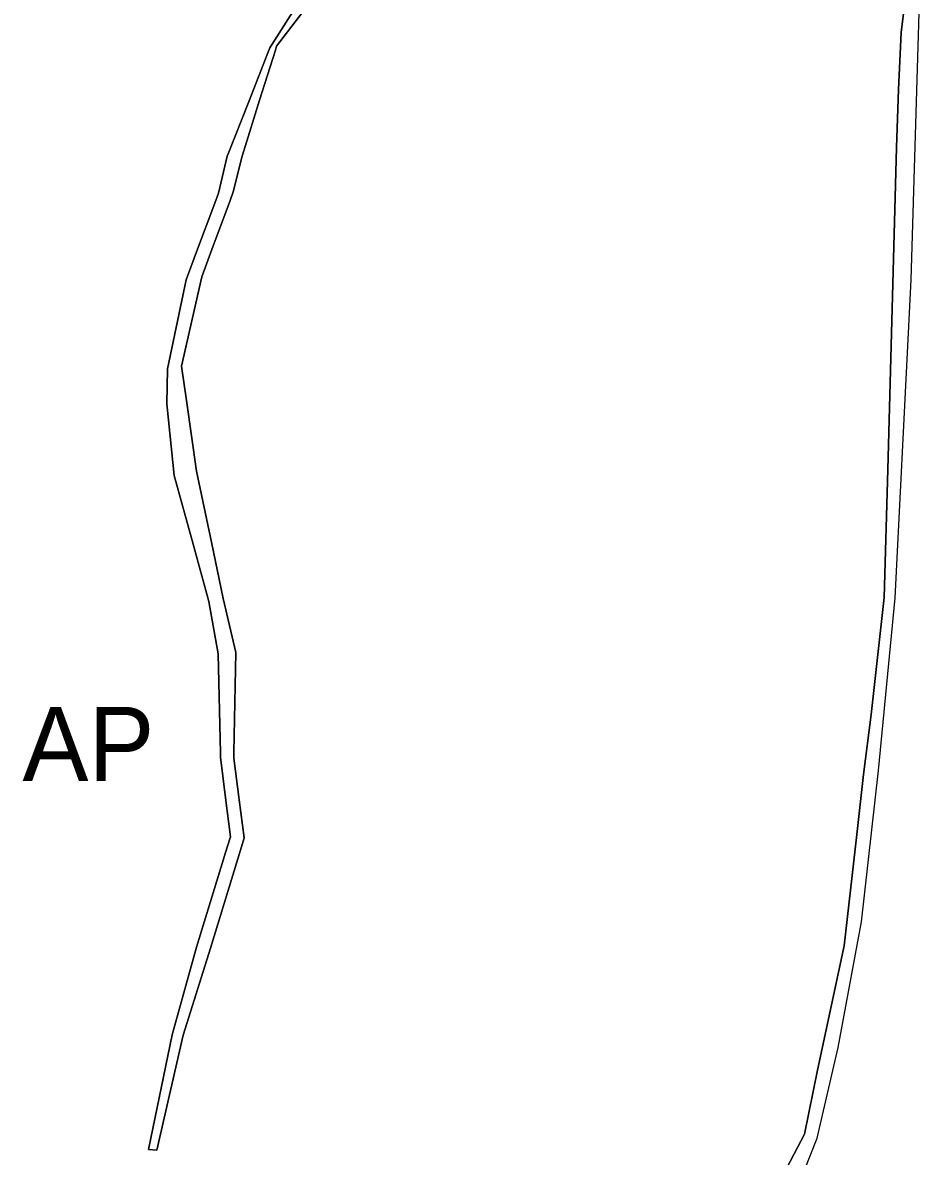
# Model space of a CAD drawing. Extents: x -555509 to -553005, y -1186756 to -1182560.
# Drawn here: x -553439.4 to -553269.7, y -1183694.3 to -1183479.6 of the extents above; entities that cross this region are included whole.
import ezdxf

# ---------------------------------------------------------------- set-up
doc = ezdxf.new("R2010")
doc.units = 0
for name, color, linetype in [('Level 26', 7, 'Continuous'), ('Level 59', 7, 'Continuous'), ('OBRYS_PLOCH', 7, 'Continuous'), ('stav_AP', 7, 'Continuous'), ('stav_ZK', 7, 'Continuous')]:
    doc.layers.add(name, color=color, linetype=linetype)

msp = doc.modelspace()

# ---------------------------------------------------------------- linework, layer by layer
at = {"layer": 'Level 26'}
for p, q in [((-553271.84, -1183471.16), (-553273.12, -1183481.48)), ((-553271.2, -1183528.31), (-553269.67, -1183477.71)), ((-553273.12, -1183481.48), (-553273.58, -1183492.27)), ((-553273.58, -1183492.27), (-553273.96, -1183503.21)), ((-553273.96, -1183503.21), (-553274.81, -1183533.7)), ((-553274.27, -1183588.5), (-553271.2, -1183528.31)), ((-553274.81, -1183533.7), (-553275.62, -1183564.2)), ((-553275.62, -1183564.2), (-553276.31, -1183588.43)), ((-553276.31, -1183588.43), (-553278.78, -1183610.59)), ((-553277.37, -1183621.21), (-553274.27, -1183588.5)), ((-553278.78, -1183610.59), (-553280.24, -1183621.99)), ((-553280.24, -1183621.99), (-553281.51, -1183633.35)), ((-553280.64, -1183649.89), (-553277.37, -1183621.21)), ((-553281.51, -1183633.35), (-553283.92, -1183654.41)), ((-553285.02, -1183673.67), (-553280.64, -1183649.89)), ((-553283.92, -1183654.41), (-553288.93, -1183677.96)), ((-553289.02, -1183690.81), (-553285.02, -1183673.67)), ((-553288.93, -1183677.96), (-553291.41, -1183690.06)), ((-553291.41, -1183690.06), (-553302.02, -1183710.22))]:
    msp.add_line(p, q, dxfattribs=at)
msp.add_lwpolyline([(-553303.19, -1183731.69), (-553297.87, -1183713.28), (-553289.02, -1183690.81)], dxfattribs=at)
at = {"layer": 'OBRYS_PLOCH'}
for p, q in [((-553391.32, -1183484.04), (-553380.16, -1183469.46)), ((-553380.16, -1183469.46), (-553391.32, -1183484.04)), ((-553383.76, -1183470.34), (-553392.58, -1183484.35)), ((-553392.58, -1183484.35), (-553383.76, -1183470.34)), ((-553271.84, -1183471.16), (-553273.12, -1183481.48)), ((-553273.12, -1183481.48), (-553271.84, -1183471.16)), ((-553271.2, -1183528.31), (-553269.67, -1183477.71)), ((-553273.12, -1183481.48), (-553273.58, -1183492.27)), ((-553273.58, -1183492.27), (-553273.12, -1183481.48)), ((-553394.53, -1183494.29), (-553391.55, -1183484.77)), ((-553391.55, -1183484.77), (-553394.53, -1183494.29)), ((-553392.58, -1183484.35), (-553392.85, -1183485.02)), ((-553392.85, -1183485.02), (-553392.58, -1183484.35)), ((-553391.55, -1183484.77), (-553391.32, -1183484.04)), ((-553391.32, -1183484.04), (-553391.55, -1183484.77)), ((-553392.85, -1183485.02), (-553396.66, -1183494.7)), ((-553396.66, -1183494.7), (-553392.85, -1183485.02)), ((-553273.58, -1183492.27), (-553273.96, -1183503.21)), ((-553273.96, -1183503.21), (-553273.58, -1183492.27)), ((-553396.66, -1183494.7), (-553400.49, -1183504.4)), ((-553400.49, -1183504.4), (-553396.66, -1183494.7)), ((-553397.53, -1183503.84), (-553394.53, -1183494.29)), ((-553394.53, -1183494.29), (-553397.53, -1183503.84)), ((-553397.9, -1183505.04), (-553397.53, -1183503.84)), ((-553397.53, -1183503.84), (-553397.9, -1183505.04)), ((-553273.96, -1183503.21), (-553274.81, -1183533.7)), ((-553274.81, -1183533.7), (-553273.96, -1183503.21)), ((-553400.66, -1183504.85), (-553402.33, -1183511.88)), ((-553402.33, -1183511.88), (-553400.66, -1183504.85)), ((-553400.49, -1183504.4), (-553400.66, -1183504.85)), ((-553400.66, -1183504.85), (-553400.49, -1183504.4)), ((-553399.46, -1183511.44), (-553397.9, -1183505.04)), ((-553397.9, -1183505.04), (-553399.46, -1183511.44)), ((-553402.33, -1183511.88), (-553403.02, -1183513.75)), ((-553403.02, -1183513.75), (-553402.33, -1183511.88)), ((-553400.14, -1183513.27), (-553399.46, -1183511.44)), ((-553399.46, -1183511.44), (-553400.14, -1183513.27)), ((-553403.02, -1183513.75), (-553406.46, -1183522.99)), ((-553406.46, -1183522.99), (-553403.02, -1183513.75)), ((-553403.59, -1183522.56), (-553400.14, -1183513.27)), ((-553400.14, -1183513.27), (-553403.59, -1183522.56)), ((-553406.46, -1183522.99), (-553408.45, -1183528.32)), ((-553408.45, -1183528.32), (-553406.46, -1183522.99)), ((-553405.5, -1183527.73), (-553403.59, -1183522.56)), ((-553403.59, -1183522.56), (-553405.5, -1183527.73)), ((-553409.35, -1183544.62), (-553405.5, -1183527.73)), ((-553405.5, -1183527.73), (-553409.35, -1183544.62)), ((-553408.45, -1183528.32), (-553412, -1183545.16)), ((-553412, -1183545.16), (-553408.45, -1183528.32)), ((-553274.27, -1183588.5), (-553271.2, -1183528.31)), ((-553274.81, -1183533.7), (-553275.62, -1183564.2)), ((-553275.62, -1183564.2), (-553274.81, -1183533.7)), ((-553408.4, -1183551.17), (-553409.35, -1183544.62)), ((-553409.35, -1183544.62), (-553408.4, -1183551.17)), ((-553412, -1183545.16), (-553412.1, -1183551.77)), ((-553412.1, -1183551.77), (-553412, -1183545.16)), ((-553406.47, -1183564.52), (-553408.4, -1183551.17)), ((-553408.4, -1183551.17), (-553406.47, -1183564.52)), ((-553412.1, -1183551.77), (-553410.69, -1183565.36)), ((-553410.69, -1183565.36), (-553412.1, -1183551.77)), ((-553275.62, -1183564.2), (-553276.31, -1183588.43)), ((-553276.31, -1183588.43), (-553275.62, -1183564.2)), ((-553410.69, -1183565.36), (-553407.14, -1183578.33)), ((-553407.14, -1183578.33), (-553410.69, -1183565.36)), ((-553403.65, -1183577.98), (-553406.47, -1183564.52)), ((-553406.47, -1183564.52), (-553403.65, -1183577.98)), ((-553407.14, -1183578.33), (-553404.16, -1183589.2)), ((-553404.16, -1183589.2), (-553407.14, -1183578.33)), ((-553401.41, -1183588.64), (-553403.65, -1183577.98)), ((-553403.65, -1183577.98), (-553401.41, -1183588.64)), ((-553404.16, -1183589.2), (-553402.35, -1183599.13)), ((-553402.35, -1183599.13), (-553404.16, -1183589.2)), ((-553399.06, -1183598.85), (-553401.41, -1183588.64)), ((-553401.41, -1183588.64), (-553399.06, -1183598.85)), ((-553276.31, -1183588.43), (-553278.78, -1183610.59)), ((-553278.78, -1183610.59), (-553276.31, -1183588.43)), ((-553277.37, -1183621.21), (-553274.27, -1183588.5)), ((-553402.35, -1183599.13), (-553401.96, -1183617.95)), ((-553401.96, -1183617.95), (-553402.35, -1183599.13)), ((-553399.39, -1183617.8), (-553399.06, -1183598.85)), ((-553399.06, -1183598.85), (-553399.39, -1183617.8)), ((-553278.78, -1183610.59), (-553280.24, -1183621.99)), ((-553280.24, -1183621.99), (-553278.78, -1183610.59)), ((-553401.96, -1183617.95), (-553401.94, -1183618.66)), ((-553401.94, -1183618.66), (-553401.96, -1183617.95)), ((-553399.41, -1183618.84), (-553399.39, -1183617.8)), ((-553399.39, -1183617.8), (-553399.41, -1183618.84)), ((-553401.94, -1183618.66), (-553400.91, -1183626.86)), ((-553400.91, -1183626.86), (-553401.94, -1183618.66)), ((-553398.39, -1183626.76), (-553399.41, -1183618.84)), ((-553399.41, -1183618.84), (-553398.39, -1183626.76)), ((-553280.24, -1183621.99), (-553281.51, -1183633.35)), ((-553281.51, -1183633.35), (-553280.24, -1183621.99)), ((-553280.64, -1183649.89), (-553277.37, -1183621.21)), ((-553400.91, -1183626.86), (-553400.05, -1183633.75)), ((-553400.05, -1183633.75), (-553400.91, -1183626.86)), ((-553397.45, -1183633.93), (-553398.39, -1183626.76)), ((-553398.39, -1183626.76), (-553397.45, -1183633.93)), ((-553400.05, -1183633.75), (-553400.66, -1183635.71)), ((-553400.66, -1183635.71), (-553400.05, -1183633.75)), ((-553397.98, -1183635.66), (-553397.45, -1183633.93)), ((-553397.45, -1183633.93), (-553397.98, -1183635.66)), ((-553281.51, -1183633.35), (-553283.92, -1183654.41)), ((-553283.92, -1183654.41), (-553281.51, -1183633.35)), ((-553400.66, -1183635.71), (-553406.51, -1183654.66)), ((-553406.51, -1183654.66), (-553400.66, -1183635.71)), ((-553403.82, -1183654.85), (-553397.98, -1183635.66)), ((-553397.98, -1183635.66), (-553403.82, -1183654.85)), ((-553285.02, -1183673.67), (-553280.64, -1183649.89)), ((-553283.92, -1183654.41), (-553288.93, -1183677.96)), ((-553288.93, -1183677.96), (-553283.92, -1183654.41)), ((-553406.51, -1183654.66), (-553411.11, -1183671.23)), ((-553411.11, -1183671.23), (-553406.51, -1183654.66)), ((-553408.98, -1183671.33), (-553403.82, -1183654.85)), ((-553403.82, -1183654.85), (-553408.98, -1183671.33)), ((-553411.11, -1183671.23), (-553415.59, -1183693)), ((-553415.59, -1183693), (-553411.11, -1183671.23)), ((-553414, -1183693.11), (-553408.98, -1183671.33)), ((-553408.98, -1183671.33), (-553414, -1183693.11)), ((-553289.02, -1183690.81), (-553285.02, -1183673.67)), ((-553288.93, -1183677.96), (-553291.41, -1183690.06)), ((-553291.41, -1183690.06), (-553288.93, -1183677.96)), ((-553291.41, -1183690.06), (-553302.02, -1183710.22)), ((-553302.02, -1183710.22), (-553291.41, -1183690.06)), ((-553415.59, -1183693), (-553414, -1183693.11)), ((-553414, -1183693.11), (-553415.59, -1183693))]:
    msp.add_line(p, q, dxfattribs=at)
msp.add_lwpolyline([(-553303.19, -1183731.69), (-553297.87, -1183713.28), (-553289.02, -1183690.81)], dxfattribs=at)
at = {"layer": 'stav_AP'}
for p, q in [((-553380.16, -1183469.46), (-553391.32, -1183484.04)), ((-553392.58, -1183484.35), (-553383.76, -1183470.34)), ((-553273.12, -1183481.48), (-553271.84, -1183471.16)), ((-553273.58, -1183492.27), (-553273.12, -1183481.48)), ((-553391.55, -1183484.77), (-553394.53, -1183494.29)), ((-553392.85, -1183485.02), (-553392.58, -1183484.35)), ((-553391.32, -1183484.04), (-553391.55, -1183484.77)), ((-553396.66, -1183494.7), (-553392.85, -1183485.02)), ((-553273.96, -1183503.21), (-553273.58, -1183492.27)), ((-553400.49, -1183504.4), (-553396.66, -1183494.7)), ((-553394.53, -1183494.29), (-553397.53, -1183503.84)), ((-553397.53, -1183503.84), (-553397.9, -1183505.04)), ((-553274.81, -1183533.7), (-553273.96, -1183503.21)), ((-553402.33, -1183511.88), (-553400.66, -1183504.85)), ((-553400.66, -1183504.85), (-553400.49, -1183504.4)), ((-553397.9, -1183505.04), (-553399.46, -1183511.44)), ((-553403.02, -1183513.75), (-553402.33, -1183511.88)), ((-553399.46, -1183511.44), (-553400.14, -1183513.27)), ((-553406.46, -1183522.99), (-553403.02, -1183513.75)), ((-553400.14, -1183513.27), (-553403.59, -1183522.56)), ((-553408.45, -1183528.32), (-553406.46, -1183522.99)), ((-553403.59, -1183522.56), (-553405.5, -1183527.73)), ((-553405.5, -1183527.73), (-553409.35, -1183544.62)), ((-553412, -1183545.16), (-553408.45, -1183528.32)), ((-553275.62, -1183564.2), (-553274.81, -1183533.7)), ((-553409.35, -1183544.62), (-553408.4, -1183551.17)), ((-553412.1, -1183551.77), (-553412, -1183545.16)), ((-553408.4, -1183551.17), (-553406.47, -1183564.52)), ((-553410.69, -1183565.36), (-553412.1, -1183551.77)), ((-553276.31, -1183588.43), (-553275.62, -1183564.2)), ((-553407.14, -1183578.33), (-553410.69, -1183565.36)), ((-553406.47, -1183564.52), (-553403.65, -1183577.98)), ((-553404.16, -1183589.2), (-553407.14, -1183578.33)), ((-553403.65, -1183577.98), (-553401.41, -1183588.64)), ((-553402.35, -1183599.13), (-553404.16, -1183589.2)), ((-553401.41, -1183588.64), (-553399.06, -1183598.85)), ((-553278.78, -1183610.59), (-553276.31, -1183588.43)), ((-553401.96, -1183617.95), (-553402.35, -1183599.13)), ((-553399.06, -1183598.85), (-553399.39, -1183617.8)), ((-553280.24, -1183621.99), (-553278.78, -1183610.59)), ((-553401.94, -1183618.66), (-553401.96, -1183617.95)), ((-553399.39, -1183617.8), (-553399.41, -1183618.84)), ((-553400.91, -1183626.86), (-553401.94, -1183618.66)), ((-553399.41, -1183618.84), (-553398.39, -1183626.76)), ((-553281.51, -1183633.35), (-553280.24, -1183621.99)), ((-553400.05, -1183633.75), (-553400.91, -1183626.86)), ((-553398.39, -1183626.76), (-553397.45, -1183633.93)), ((-553400.66, -1183635.71), (-553400.05, -1183633.75)), ((-553397.45, -1183633.93), (-553397.98, -1183635.66)), ((-553283.92, -1183654.41), (-553281.51, -1183633.35)), ((-553406.51, -1183654.66), (-553400.66, -1183635.71)), ((-553397.98, -1183635.66), (-553403.82, -1183654.85)), ((-553288.93, -1183677.96), (-553283.92, -1183654.41)), ((-553411.11, -1183671.23), (-553406.51, -1183654.66)), ((-553403.82, -1183654.85), (-553408.98, -1183671.33)), ((-553415.59, -1183693), (-553411.11, -1183671.23)), ((-553408.98, -1183671.33), (-553414, -1183693.11)), ((-553291.41, -1183690.06), (-553288.93, -1183677.96)), ((-553302.02, -1183710.22), (-553291.41, -1183690.06)), ((-553414, -1183693.11), (-553415.59, -1183693))]:
    msp.add_line(p, q, dxfattribs=at)
at = {"layer": 'stav_ZK'}
for p, q in [((-553391.32, -1183484.04), (-553380.16, -1183469.46)), ((-553383.76, -1183470.34), (-553392.58, -1183484.35)), ((-553394.53, -1183494.29), (-553391.55, -1183484.77)), ((-553392.58, -1183484.35), (-553392.85, -1183485.02)), ((-553391.55, -1183484.77), (-553391.32, -1183484.04)), ((-553392.85, -1183485.02), (-553396.66, -1183494.7)), ((-553396.66, -1183494.7), (-553400.49, -1183504.4)), ((-553397.53, -1183503.84), (-553394.53, -1183494.29)), ((-553397.9, -1183505.04), (-553397.53, -1183503.84)), ((-553400.66, -1183504.85), (-553402.33, -1183511.88)), ((-553400.49, -1183504.4), (-553400.66, -1183504.85)), ((-553399.46, -1183511.44), (-553397.9, -1183505.04)), ((-553402.33, -1183511.88), (-553403.02, -1183513.75)), ((-553400.14, -1183513.27), (-553399.46, -1183511.44)), ((-553403.02, -1183513.75), (-553406.46, -1183522.99)), ((-553403.59, -1183522.56), (-553400.14, -1183513.27)), ((-553406.46, -1183522.99), (-553408.45, -1183528.32)), ((-553405.5, -1183527.73), (-553403.59, -1183522.56)), ((-553409.35, -1183544.62), (-553405.5, -1183527.73)), ((-553408.45, -1183528.32), (-553412, -1183545.16)), ((-553408.4, -1183551.17), (-553409.35, -1183544.62)), ((-553412, -1183545.16), (-553412.1, -1183551.77)), ((-553406.47, -1183564.52), (-553408.4, -1183551.17)), ((-553412.1, -1183551.77), (-553410.69, -1183565.36)), ((-553410.69, -1183565.36), (-553407.14, -1183578.33)), ((-553403.65, -1183577.98), (-553406.47, -1183564.52)), ((-553407.14, -1183578.33), (-553404.16, -1183589.2)), ((-553401.41, -1183588.64), (-553403.65, -1183577.98)), ((-553404.16, -1183589.2), (-553402.35, -1183599.13)), ((-553399.06, -1183598.85), (-553401.41, -1183588.64)), ((-553402.35, -1183599.13), (-553401.96, -1183617.95)), ((-553399.39, -1183617.8), (-553399.06, -1183598.85)), ((-553401.96, -1183617.95), (-553401.94, -1183618.66)), ((-553399.41, -1183618.84), (-553399.39, -1183617.8)), ((-553401.94, -1183618.66), (-553400.91, -1183626.86)), ((-553398.39, -1183626.76), (-553399.41, -1183618.84)), ((-553400.91, -1183626.86), (-553400.05, -1183633.75)), ((-553397.45, -1183633.93), (-553398.39, -1183626.76)), ((-553400.05, -1183633.75), (-553400.66, -1183635.71)), ((-553397.98, -1183635.66), (-553397.45, -1183633.93)), ((-553400.66, -1183635.71), (-553406.51, -1183654.66)), ((-553403.82, -1183654.85), (-553397.98, -1183635.66)), ((-553406.51, -1183654.66), (-553411.11, -1183671.23)), ((-553408.98, -1183671.33), (-553403.82, -1183654.85)), ((-553411.11, -1183671.23), (-553415.59, -1183693)), ((-553414, -1183693.11), (-553408.98, -1183671.33)), ((-553415.59, -1183693), (-553414, -1183693.11))]:
    msp.add_line(p, q, dxfattribs=at)

# ---------------------------------------------------------------- texts
at = {"layer": 'Level 59'}
msp.add_text('AP', height=14, dxfattribs=at).set_placement((-553439.42, -1183623.16))

doc.saveas('drawing.dxf')
